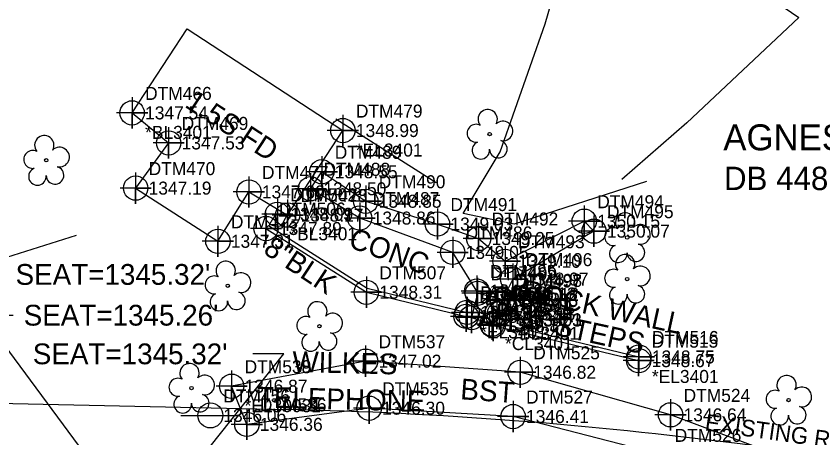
# Model space of a CAD drawing. Extents: x 1303760 to 1305114, y 904598 to 905144.
# Drawn here: x 1304338.5 to 1304493.6, y 904835.9 to 904917.1 of the extents above; entities that cross this region are included whole.
import ezdxf

# ---------------------------------------------------------------- set-up
doc = ezdxf.new("R2010")
doc.units = 0
for name, color, linetype in [('Exist Building', 7, 'Continuous'), ('Exist Building Cogo Elevation', 7, 'Continuous'), ('Exist Building Cogo Number', 7, 'Continuous'), ('Exist Building Cogo Point CELL', 7, 'Continuous'), ('Exist Building Text', 7, 'Continuous'), ('Exist Property Deed Book Text', 7, 'Continuous'), ('Exist Property Owner Text', 7, 'Continuous'), ('Exist Right of Way Line', 7, 'Continuous'), ('Exist Right of Way Line Text', 7, 'Continuous'), ('Exist Roads EOP Other', 7, 'Continuous'), ('Exist Roads EOP Other Cogo Comment', 7, 'Continuous'), ('Exist Roads EOP Other Cogo Elevation', 7, 'Continuous'), ('Exist Roads EOP Other Cogo Number', 7, 'Continuous'), ('Exist Roads EOP Other Cogo Point CELL', 7, 'Continuous'), ('Exist Roads EOP Other Text', 7, 'Continuous'), ('Exist Structure Major Bridge Seat Top Elevation', 7, 'Continuous'), ('Exist Utilities Telephone Pole CELL', 7, 'Continuous'), ('Exist Utilities Telephone Pole Cogo Elevation', 7, 'Continuous'), ('Exist Utilities Telephone Pole Cogo Number', 7, 'Continuous'), ('Exist Utilities Telephone Pole Text', 7, 'Continuous'), ('Exist Vegetation Tree CELL', 7, 'Continuous'), ('Exist Vegetation Woods Line', 7, 'Continuous')]:
    doc.layers.add(name, color=color, linetype=linetype)

msp = doc.modelspace()

# ---------------------------------------------------------------- linework, layer by layer
at = {"layer": 'Exist Building'}
for p, q in [((1304371.34, 904914.64), (1304401.32, 904895.06)), ((1304399.94, 904897.3), (1304419.25, 904885.03)), ((1304386.99, 904876.78), (1304406.02, 904864.69)), ((1304406.02, 904864.69), (1304425.21, 904860.05)), ((1304431.4, 904859.71), (1304430.89, 904858.08)), ((1304430.89, 904858.08), (1304458.26, 904851.47))]:
    msp.add_line(p, q, dxfattribs=at)
for points in [[(1304360.78, 904898.46), (1304371.34, 904914.64)], [(1304360.78, 904898.46), (1304367.81, 904892.68), (1304361.46, 904883.98), (1304377.28, 904873.74), (1304383.25, 904883.24), (1304390.69, 904878.78), (1304401.32, 904895.06)], [(1304386.99, 904876.78), (1304386.53, 904876.2)], [(1304386.53, 904876.2), (1304405.84, 904863.93)], [(1304405.84, 904863.93), (1304425.03, 904859.29)], [(1304432.01, 904862.46), (1304427.21, 904863.73), (1304426.06, 904859.05), (1304430.01, 904857.79), (1304432.01, 904862.46)], [(1304425.03, 904859.29), (1304425.22, 904860.05)], [(1304430.95, 904859.85), (1304430.22, 904857.52)], [(1304431.42, 904859.77), (1304430.95, 904859.85)], [(1304430.22, 904857.52), (1304458.2, 904850.76)], [(1304458.2, 904850.76), (1304458.26, 904851.47)]]:
    msp.add_lwpolyline(points, dxfattribs=at)
at = {"layer": 'Exist Building Cogo Point CELL'}
for points in [[(1304360.78, 904901.46), (1304360.78, 904895.46), (1304360.78, 904898.46), (1304363.78, 904898.46), (1304357.78, 904898.46)], [(1304401.32, 904898.06), (1304401.32, 904892.06), (1304401.32, 904895.06), (1304404.32, 904895.06), (1304398.32, 904895.06)], [(1304367.81, 904895.68), (1304367.81, 904889.68), (1304367.81, 904892.68), (1304370.81, 904892.68), (1304364.81, 904892.68)], [(1304361.46, 904886.98), (1304361.46, 904880.98), (1304361.46, 904883.98), (1304364.46, 904883.98), (1304358.46, 904883.98)], [(1304383.25, 904886.24), (1304383.25, 904880.24), (1304383.25, 904883.24), (1304386.25, 904883.24), (1304380.25, 904883.24)], [(1304388.72, 904881.94), (1304388.72, 904875.94), (1304388.72, 904878.94), (1304391.72, 904878.94), (1304385.72, 904878.94)], [(1304390.69, 904881.78), (1304390.69, 904875.78), (1304390.69, 904878.78), (1304393.69, 904878.78), (1304387.69, 904878.78)], [(1304386.53, 904879.2), (1304386.53, 904873.2), (1304386.53, 904876.2), (1304389.53, 904876.2), (1304383.53, 904876.2)], [(1304377.28, 904876.74), (1304377.28, 904870.74), (1304377.28, 904873.74), (1304380.28, 904873.74), (1304374.28, 904873.74)], [(1304405.84, 904866.93), (1304405.84, 904860.93), (1304405.84, 904863.93), (1304408.84, 904863.93), (1304402.84, 904863.93)], [(1304427.21, 904866.73), (1304427.21, 904860.73), (1304427.21, 904863.73), (1304430.21, 904863.73), (1304424.21, 904863.73)], [(1304432.01, 904865.46), (1304432.01, 904859.46), (1304432.01, 904862.46), (1304435.01, 904862.46), (1304429.01, 904862.46)], [(1304425.03, 904862.29), (1304425.03, 904856.29), (1304425.03, 904859.29), (1304428.03, 904859.29), (1304422.03, 904859.29)], [(1304425.22, 904863.05), (1304425.22, 904857.05), (1304425.22, 904860.05), (1304428.22, 904860.05), (1304422.22, 904860.05)], [(1304426.06, 904862.05), (1304426.06, 904856.05), (1304426.06, 904859.05), (1304429.06, 904859.05), (1304423.06, 904859.05)], [(1304430.95, 904862.85), (1304430.95, 904856.85), (1304430.95, 904859.85), (1304433.95, 904859.85), (1304427.95, 904859.85)], [(1304431.42, 904862.77), (1304431.42, 904856.77), (1304431.42, 904859.77), (1304434.42, 904859.77), (1304428.42, 904859.77)], [(1304430.01, 904860.79), (1304430.01, 904854.79), (1304430.01, 904857.79), (1304433.01, 904857.79), (1304427.01, 904857.79)], [(1304430.22, 904860.52), (1304430.22, 904854.52), (1304430.22, 904857.52), (1304433.22, 904857.52), (1304427.22, 904857.52)], [(1304458.26, 904854.47), (1304458.26, 904848.47), (1304458.26, 904851.47), (1304461.26, 904851.47), (1304455.26, 904851.47)], [(1304458.2, 904853.76), (1304458.2, 904847.76), (1304458.2, 904850.76), (1304461.2, 904850.76), (1304455.2, 904850.76)]]:
    msp.add_lwpolyline(points, dxfattribs=at)
for centre in [(1304360.78, 904898.46), (1304401.32, 904895.06), (1304367.81, 904892.68), (1304361.46, 904883.98), (1304383.25, 904883.24), (1304388.72, 904878.94), (1304390.69, 904878.78), (1304386.53, 904876.2), (1304377.28, 904873.74), (1304405.84, 904863.93), (1304427.21, 904863.73), (1304432.01, 904862.46), (1304425.22, 904860.05), (1304430.95, 904859.85), (1304431.42, 904859.77), (1304425.03, 904859.29), (1304426.06, 904859.05), (1304430.01, 904857.79), (1304430.22, 904857.52), (1304458.2, 904850.76), (1304458.26, 904851.47)]:
    msp.add_circle(centre, 2.34, dxfattribs=at)
at = {"layer": 'Exist Right of Way Line'}
msp.add_line((1304243.26, 904844.66), (1304390.68, 904841.34), dxfattribs=at)
msp.add_arc((1304372.37, 904026.26), 815.29, 76.43947, 88.71327, dxfattribs=at)
at = {"layer": 'Exist Roads EOP Other'}
for points in [[(1304427.08, 904864.17), (1304422.44, 904871.6), (1304404.56, 904878.21), (1304395.09, 904883.85), (1304397.26, 904887.12), (1304405.72, 904881.45), (1304419.51, 904877.06), (1304427.43, 904874.28), (1304432.51, 904869.89), (1304447.74, 904877.61), (1304449.61, 904875.69), (1304433.98, 904866.46), (1304431.95, 904862.33)], [(1304491.2, 904824.88), (1304492.04, 904829.93), (1304464.35, 904840.33), (1304435.43, 904848.52), (1304405.68, 904850.66), (1304379.92, 904845.84)], [(1304491.18, 904824.88), (1304462.64, 904832.63), (1304434.06, 904840), (1304406.37, 904841.61), (1304382.85, 904838.5), (1304379.92, 904845.84)]]:
    msp.add_lwpolyline(points, dxfattribs=at)
at = {"layer": 'Exist Roads EOP Other Cogo Point CELL'}
for points in [[(1304397.26, 904890.12), (1304397.26, 904884.12), (1304397.26, 904887.12), (1304400.26, 904887.12), (1304394.26, 904887.12)], [(1304395.09, 904886.85), (1304395.09, 904880.85), (1304395.09, 904883.85), (1304398.09, 904883.85), (1304392.09, 904883.85)], [(1304405.72, 904884.45), (1304405.72, 904878.45), (1304405.72, 904881.45), (1304408.72, 904881.45), (1304402.72, 904881.45)], [(1304404.56, 904881.21), (1304404.56, 904875.21), (1304404.56, 904878.21), (1304407.56, 904878.21), (1304401.56, 904878.21)], [(1304447.74, 904880.61), (1304447.74, 904874.61), (1304447.74, 904877.61), (1304450.74, 904877.61), (1304444.74, 904877.61)], [(1304419.51, 904880.06), (1304419.51, 904874.06), (1304419.51, 904877.06), (1304422.51, 904877.06), (1304416.51, 904877.06)], [(1304449.61, 904878.69), (1304449.61, 904872.69), (1304449.61, 904875.69), (1304452.61, 904875.69), (1304446.61, 904875.69)], [(1304427.43, 904877.28), (1304427.43, 904871.28), (1304427.43, 904874.28), (1304430.43, 904874.28), (1304424.43, 904874.28)], [(1304422.44, 904874.6), (1304422.44, 904868.6), (1304422.44, 904871.6), (1304425.44, 904871.6), (1304419.44, 904871.6)], [(1304432.51, 904872.89), (1304432.51, 904866.89), (1304432.51, 904869.89), (1304435.51, 904869.89), (1304429.51, 904869.89)], [(1304433.98, 904869.46), (1304433.98, 904863.46), (1304433.98, 904866.46), (1304436.98, 904866.46), (1304430.98, 904866.46)], [(1304427.08, 904867.17), (1304427.08, 904861.17), (1304427.08, 904864.17), (1304430.08, 904864.17), (1304424.08, 904864.17)], [(1304431.95, 904865.33), (1304431.95, 904859.33), (1304431.95, 904862.33), (1304434.95, 904862.33), (1304428.95, 904862.33)], [(1304405.68, 904853.66), (1304405.68, 904847.66), (1304405.68, 904850.66), (1304408.68, 904850.66), (1304402.68, 904850.66)], [(1304435.43, 904851.52), (1304435.43, 904845.52), (1304435.43, 904848.52), (1304438.43, 904848.52), (1304432.43, 904848.52)], [(1304379.92, 904848.84), (1304379.92, 904842.84), (1304379.92, 904845.84), (1304382.92, 904845.84), (1304376.92, 904845.84)], [(1304379.92, 904848.84), (1304379.92, 904842.84), (1304379.92, 904845.84), (1304382.92, 904845.84), (1304376.92, 904845.84)], [(1304406.37, 904844.61), (1304406.37, 904838.61), (1304406.37, 904841.61), (1304409.37, 904841.61), (1304403.37, 904841.61)], [(1304464.35, 904843.33), (1304464.35, 904837.33), (1304464.35, 904840.33), (1304467.35, 904840.33), (1304461.35, 904840.33)], [(1304434.06, 904843), (1304434.06, 904837), (1304434.06, 904840), (1304437.06, 904840), (1304431.06, 904840)], [(1304382.85, 904841.5), (1304382.85, 904835.5), (1304382.85, 904838.5), (1304385.85, 904838.5), (1304379.85, 904838.5)]]:
    msp.add_lwpolyline(points, dxfattribs=at)
for centre in [(1304397.26, 904887.12), (1304395.09, 904883.85), (1304405.72, 904881.45), (1304404.56, 904878.21), (1304419.51, 904877.06), (1304447.74, 904877.61), (1304449.61, 904875.69), (1304427.43, 904874.28), (1304422.44, 904871.6), (1304432.51, 904869.89), (1304433.98, 904866.46), (1304427.08, 904864.17), (1304431.95, 904862.33), (1304405.68, 904850.66), (1304435.43, 904848.52), (1304379.92, 904845.84), (1304379.92, 904845.84), (1304406.37, 904841.61), (1304434.06, 904840), (1304464.35, 904840.33), (1304382.85, 904838.5)]:
    msp.add_circle(centre, 2.34, dxfattribs=at)
at = {"layer": 'Exist Structure Major Bridge Seat Top Elevation'}
for points in [[(1304353.73, 904830.05), (1304331.93, 904859.51), (1304337.93, 904859.51)], [(1304371.82, 904829.26), (1304389.99, 904852.07), (1304383.99, 904852.07)]]:
    msp.add_lwpolyline(points, dxfattribs=at)
at = {"layer": 'Exist Utilities Telephone Pole CELL'}
for p, q in [((1304370.16, 904840.21), (1304381.49, 904840.21)), ((1304375.83, 904840.21), (1304375.83, 904840.21))]:
    msp.add_line(p, q, dxfattribs=at)
msp.add_circle((1304375.83, 904840.21), 2.41, dxfattribs=at)
at = {"layer": 'Exist Vegetation Tree CELL'}
for p, q in [((1304429.55, 904894.38), (1304429.55, 904894.38)), ((1304344.27, 904889.35), (1304344.27, 904889.35)), ((1304456, 904874.47), (1304456, 904874.47)), ((1304379.17, 904865.19), (1304379.17, 904865.19)), ((1304456, 904866.47), (1304456, 904866.47)), ((1304396.8, 904857.39), (1304396.8, 904857.39)), ((1304372.2, 904845.49), (1304372.2, 904845.49)), ((1304487.04, 904843.18), (1304487.04, 904843.18))]:
    msp.add_line(p, q, dxfattribs=at)
for centre in [(1304429.55, 904894.38), (1304344.27, 904889.35), (1304456, 904874.47), (1304456, 904866.47), (1304379.17, 904865.19), (1304396.8, 904857.39), (1304372.2, 904845.49), (1304487.04, 904843.18)]:
    msp.add_circle(centre, 0.326, dxfattribs=at)
for centre, radius, start, end in [((1304429.17, 904897.25), 1.86, 330.1651, 219.7134), ((1304426.95, 904894.53), 1.73, 62.6636, 279.3457), ((1304432.1, 904894.97), 1.9, 257.1011, 134.1999), ((1304343.89, 904892.23), 1.86, 330.1651, 219.7134), ((1304431.23, 904891.48), 1.7, 181.2822, 74.56), ((1304346.82, 904889.94), 1.9, 257.1011, 134.1999), ((1304427.85, 904891.26), 1.69, 111.5671, 6.231), ((1304341.67, 904889.51), 1.73, 62.6636, 279.3457), ((1304342.57, 904886.23), 1.69, 111.5671, 6.231), ((1304345.95, 904886.45), 1.7, 181.2822, 74.56), ((1304455.61, 904877.35), 1.86, 330.1651, 219.7134), ((1304453.39, 904874.63), 1.73, 62.6636, 279.3457), ((1304458.55, 904875.06), 1.9, 257.1011, 134.1999), ((1304454.29, 904871.35), 1.69, 111.5671, 6.231), ((1304457.67, 904871.57), 1.7, 181.2822, 74.56), ((1304455.61, 904869.34), 1.86, 330.1651, 219.7134), ((1304378.79, 904868.06), 1.86, 330.1651, 219.7134), ((1304453.39, 904866.62), 1.73, 62.6636, 279.3457), ((1304458.55, 904867.06), 1.9, 257.1011, 134.1999), ((1304376.57, 904865.34), 1.73, 62.6636, 279.3457), ((1304381.72, 904865.78), 1.9, 257.1011, 134.1999), ((1304457.67, 904863.57), 1.7, 181.2822, 74.56), ((1304377.47, 904862.07), 1.69, 111.5671, 6.231), ((1304380.85, 904862.29), 1.7, 181.2822, 74.56), ((1304454.29, 904863.35), 1.69, 111.5671, 6.231), ((1304396.42, 904860.26), 1.86, 330.1651, 219.7134), ((1304394.2, 904857.54), 1.73, 62.6636, 279.3457), ((1304399.35, 904857.98), 1.9, 257.1011, 134.1999), ((1304395.1, 904854.27), 1.69, 111.5671, 6.231), ((1304398.48, 904854.49), 1.7, 181.2822, 74.56), ((1304371.82, 904848.36), 1.86, 330.1651, 219.7134), ((1304374.75, 904846.07), 1.9, 257.1011, 134.1999), ((1304486.66, 904846.05), 1.86, 330.1651, 219.7134), ((1304369.6, 904845.64), 1.73, 62.6636, 279.3457), ((1304484.44, 904843.33), 1.73, 62.6636, 279.3457), ((1304489.59, 904843.77), 1.9, 257.1011, 134.1999), ((1304370.5, 904842.37), 1.69, 111.5671, 6.231), ((1304373.88, 904842.59), 1.7, 181.2822, 74.56), ((1304488.72, 904840.28), 1.7, 181.2822, 74.56), ((1304485.34, 904840.06), 1.69, 111.5671, 6.231)]:
    msp.add_arc(centre, radius, start, end, dxfattribs=at)
at = {"layer": 'Exist Vegetation Woods Line'}
for points in [[(1304350.05, 904874.85), (1304321.96, 904866.03), (1304325.86, 904846.12), (1304320.53, 904845.51), (1304303.72, 904877.93), (1304289.98, 904907.28), (1304264.46, 904932.17), (1304248.68, 904952.64)], [(1304459.69, 904885.25), (1304434.27, 904877.04), (1304424.43, 904879.09), (1304431.6, 904890.99), (1304440.21, 904915.62), (1304444.11, 904929.17), (1304476.7, 904925.27), (1304489, 904916.85), (1304467.48, 904896.54), (1304454.97, 904885.66)]]:
    msp.add_lwpolyline(points, dxfattribs=at)

# ---------------------------------------------------------------- texts
at = {"layer": 'Exist Building Cogo Elevation'}
for s, p in [('1347.54', (1304363.28, 904897.21)), ('*BL3401', (1304363.28, 904893.46)), ('1348.99', (1304403.82, 904893.81)), ('1347.53', (1304370.31, 904891.43)), ('*EL3401', (1304403.82, 904890.06)), ('1347.19', (1304363.96, 904882.73)), ('1347.60', (1304385.75, 904881.99)), ('1348.09', (1304391.22, 904877.69)), ('1348.17', (1304393.19, 904877.53)), ('1347.89', (1304389.03, 904874.95)), ('*BL3401', (1304391.22, 904873.94)), ('1347.31', (1304379.78, 904872.49)), ('1348.31', (1304408.34, 904862.68)), ('1348.61', (1304429.71, 904862.48)), ('1348.63', (1304434.51, 904861.21)), ('1348.45', (1304427.53, 904858.04)), ('1348.38', (1304427.72, 904858.8)), ('1347.37', (1304428.56, 904857.8)), ('1348.99', (1304433.45, 904858.6)), ('1348.98', (1304433.92, 904858.52)), ('1347.17', (1304432.51, 904856.55)), ('1348.87', (1304432.72, 904856.27)), ('*BL3401', (1304434.51, 904857.46)), ('*EL3401', (1304427.72, 904855.05)), ('*BL3401', (1304433.92, 904854.77)), ('*CL3401', (1304432.51, 904852.8)), ('1348.75', (1304460.76, 904850.22)), ('1348.67', (1304460.7, 904849.51)), ('*EL3401', (1304460.76, 904846.47))]:
    msp.add_text(s, height=2.5, dxfattribs=at).set_placement(p)
at = {"layer": 'Exist Building Cogo Number'}
for s, p in [('DTM466', (1304363.28, 904900.96)), ('DTM479', (1304403.82, 904897.56)), ('DTM469', (1304370.31, 904895.18)), ('DTM470', (1304363.96, 904886.48)), ('DTM477', (1304385.75, 904885.74)), ('DTM502', (1304391.22, 904881.44)), ('DTM478', (1304393.19, 904881.28)), ('DTM506', (1304389.03, 904878.7)), ('DTM473', (1304379.78, 904876.24)), ('DTM507', (1304408.34, 904866.43)), ('DTM499', (1304429.71, 904866.23)), ('DTM498', (1304434.51, 904864.96)), ('DTM509', (1304427.72, 904862.55)), ('DTM508', (1304427.53, 904861.79)), ('DTM500', (1304428.56, 904861.55)), ('DTM513', (1304433.45, 904862.35)), ('DTM512', (1304433.92, 904862.27)), ('DTM501', (1304432.51, 904860.3)), ('DTM514', (1304432.72, 904860.02)), ('DTM515', (1304460.7, 904853.26)), ('DTM516', (1304460.76, 904853.97))]:
    msp.add_text(s, height=2.5, dxfattribs=at).set_placement(p)
at = {"layer": 'Exist Building Text'}
for s, rotation, p in [('1.5S FD', 326.8649, (1304370.72, 904899.71)), ('8"BLK', 326.6051, (1304385.79, 904871.59)), ('ROCK WALL', 347.679, (1304435.44, 904862.52)), ('STEPS', 347.679, (1304441.74, 904855.77))]:
    msp.add_text(s, height=4, rotation=rotation, dxfattribs=at).set_placement(p)
at = {"layer": 'Exist Property Deed Book Text'}
msp.add_text('DB 448 PG 564', height=4.5, dxfattribs=at).set_placement((1304474.62, 904883.6))
at = {"layer": 'Exist Property Owner Text'}
msp.add_text('AGNES ASHLEY', height=5, dxfattribs=at).set_placement((1304474.49, 904891.25))
at = {"layer": 'Exist Right of Way Line Text'}
msp.add_text('EXISTING R/W', height=3.2, rotation=351.9638, dxfattribs=at).set_placement((1304470.82, 904837.35))
at = {"layer": 'Exist Roads EOP Other Cogo Comment'}
for s, p in [('*BL3003', (1304429.58, 904859.17)), ('*EL3003', (1304434.45, 904857.33)), ('*EL3003', (1304382.42, 904840.84)), ('*EL30031', (1304382.42, 904840.84))]:
    msp.add_text(s, height=2.5, dxfattribs=at).set_placement(p)
at = {"layer": 'Exist Roads EOP Other Cogo Elevation'}
for s, p in [('1348.55', (1304399.76, 904885.87)), ('1348.50', (1304397.59, 904882.6)), ('1348.85', (1304408.22, 904880.2)), ('1348.86', (1304407.06, 904876.96)), ('1350.15', (1304450.24, 904876.36)), ('1349.03', (1304422.01, 904875.81)), ('1350.07', (1304452.11, 904874.44)), ('1349.25', (1304429.93, 904873.03)), ('1349.05', (1304424.94, 904870.35)), ('1349.10', (1304435.01, 904868.64)), ('1348.97', (1304436.48, 904865.21)), ('1348.86', (1304429.58, 904862.92)), ('1348.65', (1304434.45, 904861.08)), ('1347.02', (1304408.18, 904849.41)), ('1346.82', (1304437.93, 904847.27)), ('1346.87', (1304382.42, 904844.59)), ('1346.87', (1304382.42, 904844.59)), ('1346.30', (1304408.87, 904840.36)), ('1346.41', (1304436.56, 904838.75)), ('1346.64', (1304466.85, 904839.08)), ('1346.36', (1304385.35, 904837.25))]:
    msp.add_text(s, height=2.5, dxfattribs=at).set_placement(p)
at = {"layer": 'Exist Roads EOP Other Cogo Number'}
for s, p in [('DTM489', (1304399.76, 904889.62)), ('DTM488', (1304397.59, 904886.35)), ('DTM490', (1304408.22, 904883.95)), ('DTM487', (1304407.06, 904880.71)), ('DTM491', (1304422.01, 904879.56)), ('DTM494', (1304450.24, 904880.11)), ('DTM495', (1304452.11, 904878.19)), ('DTM492', (1304429.93, 904876.78)), ('DTM486', (1304424.94, 904874.1)), ('DTM493', (1304435.01, 904872.39)), ('DTM496', (1304436.48, 904868.96)), ('DTM485', (1304429.58, 904866.67)), ('DTM497', (1304434.45, 904864.83)), ('DTM537', (1304408.18, 904853.16)), ('DTM525', (1304437.93, 904851.02)), ('DTM539', (1304382.42, 904848.34)), ('DTM538', (1304382.42, 904848.34)), ('DTM535', (1304408.87, 904844.11)), ('DTM527', (1304436.56, 904842.5)), ('DTM524', (1304466.85, 904842.83)), ('DTM536', (1304385.35, 904841)), ('DTM526', (1304465.14, 904835.13))]:
    msp.add_text(s, height=2.5, dxfattribs=at).set_placement(p)
at = {"layer": 'Exist Roads EOP Other Text'}
for s, rotation, p in [('CONC', 339.7225, (1304402.17, 904872.7)), ('BST', 355.8867, (1304423.82, 904843.34))]:
    msp.add_text(s, height=4, rotation=rotation, dxfattribs=at).set_placement(p)
at = {"layer": 'Exist Structure Major Bridge Seat Top Elevation'}
for s, p in [("SEAT=1345.32'", (1304338.37, 904865.36)), ("SEAT=1345.26'", (1304339.93, 904857.51)), ("SEAT=1345.32'", (1304341.68, 904850.07))]:
    msp.add_text(s, height=4, dxfattribs=at).set_placement(p)
at = {"layer": 'Exist Utilities Telephone Pole Cogo Elevation'}
msp.add_text('1346.06', height=2.5, dxfattribs=at).set_placement((1304378.33, 904838.96))
at = {"layer": 'Exist Utilities Telephone Pole Cogo Number'}
msp.add_text('DTM456', height=2.5, dxfattribs=at).set_placement((1304378.33, 904842.71))
at = {"layer": 'Exist Utilities Telephone Pole Text'}
for s, p in [('WILKES ', (1304391.56, 904848.59)), ('TELEPHONE', (1304384.73, 904841.75))]:
    msp.add_text(s, height=4, rotation=358.6012, dxfattribs=at).set_placement(p)

doc.saveas('drawing.dxf')
